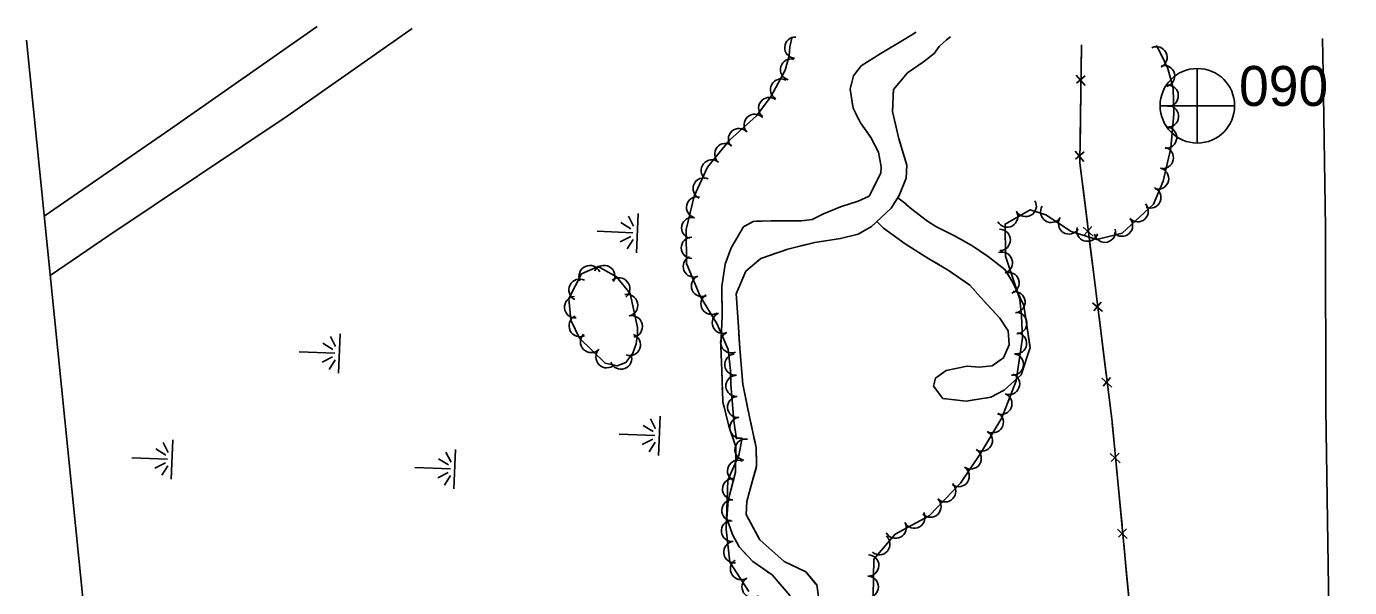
# Model space of a CAD drawing. Extents: x 296487 to 298842, y 31545 to 32791.
# Drawn here: x 297235.4 to 297732.5, y 32554.5 to 32765.2 of the extents above; entities that cross this region are included whole.
import ezdxf

# ---------------------------------------------------------------- set-up
doc = ezdxf.new("R2010")
doc.units = 0
for name, color, linetype in [('Level 11', 7, 'Continuous'), ('Level 15', 7, 'Continuous'), ('Level 18', 7, 'Continuous'), ('Level 19', 7, 'Continuous'), ('Level 4', 7, 'Continuous')]:
    doc.layers.add(name, color=color, linetype=linetype)

msp = doc.modelspace()

# ---------------------------------------------------------------- linework, layer by layer
at = {"layer": 'Level 11'}
for points in [[(297344.7, 32765.17), (297289.65, 32726.69), (297242.1, 32694)], [(297244.35, 32671.7), (297266.42, 32686.72), (297333.33, 32731.54), (297380.29, 32764.39)], [(297732.45, 31749.54), (297732.24, 31791.84), (297732.13, 31829.29), (297731.83, 31872.75), (297730.81, 31924.68), (297730.53, 31968.01), (297729.53, 32021.42), (297729.12, 32084.97), (297728.52, 32147.82), (297727.87, 32212.59), (297727.19, 32277.97), (297726.38, 32352.97), (297725.93, 32414.91), (297724.99, 32486.15), (297724.55, 32554.59), (297723.53, 32621.52), (297723.38, 32689.57), (297722.58, 32747.62), (297722.25, 32760.6)]]:
    msp.add_lwpolyline(points, dxfattribs=at)
at = {"layer": 'Level 15'}
for p, q in [((297629.82, 32746.9), (297633.09, 32743.05)), ((297633.14, 32746.68), (297629.85, 32743.86)), ((297629.43, 32718.37), (297632.7, 32714.52)), ((297632.75, 32718.15), (297629.46, 32715.33)), ((297632.38, 32689.78), (297636.14, 32686.41)), ((297635.69, 32690.02), (297632.82, 32686.77)), ((297635.89, 32661.47), (297639.66, 32658.1)), ((297639.21, 32661.7), (297636.34, 32658.46)), ((297639.41, 32633.15), (297643.17, 32629.78)), ((297642.72, 32633.39), (297639.85, 32630.14)), ((297642.59, 32604.85), (297646.26, 32601.38)), ((297645.91, 32604.99), (297642.95, 32601.83)), ((297645.32, 32576.45), (297648.98, 32572.97)), ((297648.64, 32576.59), (297645.68, 32573.43))]:
    msp.add_line(p, q, dxfattribs=at)
for points in [[(297631.76, 32758.26), (297631.16, 32714.05), (297643.24, 32616.74), (297653.23, 32512.59), (297661.32, 32428.35), (297662.84, 32377.26), (297663.95, 32360.48)], [(297631.76, 32758.26), (297631.62, 32748.07)], [(297631.53, 32741.32), (297631.37, 32729.73)], [(297631.37, 32729.73), (297631.23, 32719.53)], [(297631.31, 32712.8), (297632.74, 32701.3)], [(297632.74, 32701.3), (297634, 32691.18)], [(297634.83, 32684.49), (297636.26, 32672.98)], [(297636.26, 32672.98), (297637.52, 32662.86)], [(297638.35, 32656.17), (297639.78, 32644.67)], [(297639.78, 32644.67), (297641.03, 32634.55)], [(297641.86, 32627.86), (297643.24, 32616.74), (297643.28, 32616.35)], [(297643.28, 32616.35), (297644.25, 32606.2)], [(297644.9, 32599.49), (297646, 32587.95)], [(297646, 32587.95), (297646.98, 32577.8)], [(297647.62, 32571.09), (297648.73, 32559.55)], [(297648.73, 32559.55), (297649.7, 32549.4)]]:
    msp.add_lwpolyline(points, dxfattribs=at)
at = {"layer": 'Level 18'}
for points in [[(297523.03, 32761.23), (297522.17, 32757.58), (297521.98, 32754.18), (297520.43, 32748.77), (297515.16, 32738.99), (297509.67, 32731.67), (297499.51, 32722.5), (297491.23, 32712.4), (297486.22, 32701.52), (297483.23, 32688.9), (297483.35, 32676.23), (297488.53, 32663.94), (297494.95, 32653.42), (297499.05, 32643.89), (297499.88, 32635.95), (297500, 32630.9), (297501.11, 32617.05), (297502.18, 32610.26)], [(297553.45, 32551.33), (297553.79, 32565.22), (297561.74, 32574.51), (297574.58, 32581.47), (297586.31, 32593.65), (297593.84, 32604.78), (297601.8, 32618.18), (297607.25, 32632.15), (297609.57, 32648.32), (297609.26, 32656.37), (297608.55, 32662.73), (297603.22, 32678.98), (297603.06, 32690.98), (297612.53, 32696.33), (297618.31, 32694.41), (297627.94, 32688.18), (297637.5, 32685.21), (297646.98, 32687.57), (297658.82, 32698.46), (297662.43, 32707.11), (297665.28, 32719.47), (297666.43, 32732.34), (297666.15, 32741.99), (297664.23, 32749.36), (297661.73, 32754.64), (297660.26, 32757.33), (297659.87, 32757.97)], [(297462.25, 32664.95), (297457.09, 32671.19), (297450.23, 32675.11), (297443.93, 32672.32), (297439.22, 32662.98), (297439.88, 32654.92), (297443.21, 32648.13), (297452.77, 32638.7), (297457.33, 32637.74), (297460.61, 32638.98), (297463.17, 32642.49), (297464.44, 32646.04), (297464.98, 32649.81), (297465.01, 32652.17), (297462.25, 32664.95)], [(297504.23, 32610.58), (297503.08, 32604.19), (297498.93, 32594.78), (297498.3, 32576.43), (297499.68, 32564.06), (297506.8, 32553.05)]]:
    msp.add_lwpolyline(points, dxfattribs=at)
for centre, radius, start, end in [((297524.24, 32757.23), 3.98, 86.7381, 266.7228), ((297659.92, 32753.57), 4.01, 295.344, 115.3287), ((297522.66, 32749), 3.98, 74.0077, 253.9924), ((297662.79, 32746.55), 4.01, 284.5659, 104.5505), ((297518.88, 32741.51), 3.98, 61.6992, 241.6839), ((297664.13, 32739.18), 4.01, 271.6707, 91.6554), ((297514.43, 32734.55), 3.98, 53.1365, 233.1212), ((297664.24, 32731.42), 4.01, 264.9152, 84.8999), ((297508.99, 32728.25), 3.98, 42.0926, 222.0773), ((297503.08, 32722.91), 3.98, 42.0926, 222.0773), ((297663.53, 32723.45), 4.01, 264.9152, 84.8999), ((297497.93, 32717.28), 3.98, 50.6531, 230.6378), ((297662.29, 32715.84), 4.01, 257.0415, 77.0262), ((297492.88, 32711.12), 3.98, 50.6531, 230.6378), ((297660.5, 32708.04), 4.01, 257.0415, 77.0262), ((297489.82, 32704.35), 3.98, 65.2953, 245.28), ((297657.59, 32700.96), 4.01, 247.3036, 67.2883), ((297487.35, 32697.25), 3.98, 76.6819, 256.6666), ((297610.8, 32697.76), 4.01, 209.4808, 29.4654), ((297603.82, 32693.82), 4.01, 209.4808, 29.4654), ((297620.38, 32695.57), 4.01, 147.0797, 327.0644), ((297652.85, 32695.82), 4.01, 222.6142, 42.5988), ((297485.52, 32689.5), 3.98, 76.6819, 256.6666), ((297627.11, 32691.21), 4.01, 147.0797, 327.0644), ((297633.97, 32688.5), 4.01, 162.7475, 342.7322), ((297640.54, 32688.13), 4.01, 194.0155, 14.0001), ((297646.96, 32690.4), 4.01, 222.6142, 42.5988), ((297485.38, 32682.07), 3.98, 90.5275, 270.5122), ((297601.04, 32685.01), 4.01, 270.7619, 90.7466), ((297601.83, 32676.47), 4.01, 288.1872, 108.1719), ((297447.06, 32671.37), 4.08, 23.8806, 203.8653), ((297452.42, 32671.39), 4.08, 330.279, 150.2636), ((297486.1, 32675.06), 3.98, 112.8757, 292.8604), ((297443.27, 32666.28), 4.08, 63.2198, 243.2045), ((297458, 32666.74), 4.08, 309.6039, 129.5885), ((297489.2, 32667.72), 3.98, 112.8757, 292.8604), ((297604.33, 32668.86), 4.01, 288.1872, 108.1719), ((297461.02, 32660.51), 4.08, 282.1911, 102.1758), ((297492.78, 32660.98), 3.98, 121.3861, 301.3708), ((297606.56, 32661.63), 4.01, 276.3558, 96.3404), ((297441.62, 32659.78), 4.08, 94.7501, 274.7348), ((297443.32, 32652.75), 4.08, 116.0743, 296.059), ((297462.74, 32652.53), 4.08, 282.1911, 102.1758), ((297497.01, 32653.9), 3.98, 113.323, 293.3077), ((297607.26, 32653.81), 4.01, 272.2133, 92.1979), ((297447.6, 32646.8), 4.08, 135.4481, 315.4328), ((297462.04, 32645.67), 4.08, 250.3242, 70.3089), ((297500.16, 32646.58), 3.98, 113.323, 293.3077), ((297607.15, 32646.21), 4.01, 261.8453, 81.83), ((297453.42, 32641.07), 4.08, 135.4481, 315.4328), ((297458.73, 32640.55), 4.08, 200.7035, 20.6881), ((297501.74, 32638.21), 3.98, 95.9389, 275.9236), ((297606.01, 32638.28), 4.01, 261.8453, 81.83), ((297604.53, 32630.94), 4.01, 248.7249, 68.7096), ((297502.14, 32630.21), 3.98, 94.5901, 274.5748), ((297502.78, 32622.27), 3.98, 94.5901, 274.5748), ((297601.62, 32623.47), 4.01, 248.7249, 68.7096), ((297598.4, 32616.55), 4.01, 239.2589, 59.2435), ((297503.62, 32614.52), 3.98, 98.9439, 278.9286), ((297505.59, 32606.27), 4.01, 79.7565, 259.7411), ((297594.3, 32609.67), 4.01, 239.2589, 59.2435), ((297590.1, 32602.99), 4.01, 235.9687, 55.9534), ((297502.77, 32598.3), 4.01, 66.2074, 246.1921), ((297585.61, 32596.36), 4.01, 235.9687, 55.9534), ((297500.91, 32591.47), 4.01, 88.0653, 268.05), ((297580.53, 32590.67), 4.01, 226.0663, 46.0509), ((297500.64, 32583.46), 4.01, 88.0653, 268.05), ((297574.98, 32584.9), 4.01, 226.0663, 46.0509), ((297500.49, 32575.77), 4.01, 96.3682, 276.3529), ((297568.95, 32580.8), 4.01, 208.4825, 28.4672), ((297561.91, 32576.98), 4.01, 208.4825, 28.4672), ((297501.37, 32567.81), 4.01, 96.3682, 276.3529), ((297555.81, 32570.8), 4.01, 229.4358, 49.4205), ((297551.63, 32562.81), 4.01, 268.6008, 88.5855), ((297503.87, 32561.44), 4.01, 122.8978, 302.8825), ((297508.22, 32554.72), 4.01, 122.8978, 302.8825), ((297551.44, 32554.8), 4.01, 268.6008, 88.5855)]:
    msp.add_arc(centre, radius, start, end, dxfattribs=at)
at = {"layer": 'Level 19'}
for p, q in [((297464.58, 32680.22), (297465.18, 32695.01)), ((297462.52, 32689.17), (297458.76, 32691.53)), ((297461.56, 32694), (297463.5, 32690.23)), ((297449.82, 32688.26), (297463.23, 32687.71)), ((297462.41, 32686.37), (297458.47, 32684.33)), ((297461.06, 32681.63), (297463.3, 32685.23)), ((297352.64, 32634.97), (297353.24, 32649.75)), ((297350.58, 32643.91), (297346.82, 32646.27)), ((297349.62, 32648.74), (297351.56, 32644.97)), ((297337.88, 32643), (297351.29, 32642.45)), ((297350.46, 32641.11), (297346.53, 32639.07)), ((297349.11, 32636.37), (297351.35, 32639.97)), ((297470.81, 32613.04), (297467.05, 32615.39)), ((297469.85, 32617.87), (297471.79, 32614.1)), ((297472.87, 32604.09), (297473.47, 32618.87)), ((297289.79, 32595.24), (297290.39, 32610.02)), ((297458.11, 32612.12), (297471.52, 32611.58)), ((297470.69, 32610.24), (297466.76, 32608.19)), ((297287.73, 32604.18), (297283.97, 32606.54)), ((297286.77, 32609.01), (297288.71, 32605.24)), ((297393.01, 32605.35), (297394.95, 32601.58)), ((297396.03, 32591.58), (297396.63, 32606.36)), ((297469.35, 32605.5), (297471.58, 32609.1)), ((297275.03, 32603.27), (297288.44, 32602.72)), ((297287.61, 32601.38), (297283.68, 32599.34)), ((297286.27, 32596.65), (297288.5, 32600.24)), ((297381.27, 32599.61), (297394.68, 32599.06)), ((297393.97, 32600.52), (297390.21, 32602.88)), ((297393.85, 32597.72), (297389.92, 32595.68)), ((297392.51, 32592.99), (297394.74, 32596.58))]:
    msp.add_line(p, q, dxfattribs=at)
for points in [[(297569.6, 32763), (297565.11, 32760.32), (297556.08, 32754.87), (297549.02, 32750.34), (297546.07, 32746.63), (297544.8, 32741.57), (297545.96, 32734.47), (297548.77, 32729.03), (297552.66, 32723.54), (297555.54, 32718.04), (297556.52, 32712.45), (297556.32, 32710.21), (297554.94, 32707.1), (297552.01, 32701.43)], [(297569.6, 32763), (297565.11, 32760.32), (297556.08, 32754.87), (297549.02, 32750.34), (297546.44, 32747.09)], [(297552.88, 32690.12), (297560.32, 32696.91), (297563.33, 32701.65), (297565.95, 32708.16), (297566.14, 32713.15), (297563.12, 32722.99), (297560.78, 32733.26), (297561.08, 32741.51), (297566.42, 32747.81), (297572.42, 32751.9), (297576.44, 32755.03), (297578.3, 32757.67), (297581.01, 32760.18), (297582.53, 32761.26)], [(297561.01, 32739.67), (297561.08, 32741.51), (297566.42, 32747.81), (297572.42, 32751.9), (297576.44, 32755.03), (297578.3, 32757.67), (297581.01, 32760.18), (297582.53, 32761.26)], [(297545.26, 32743.42), (297544.8, 32741.57), (297544.81, 32741.52)], [(297545.44, 32737.67), (297545.75, 32735.74)], [(297560.79, 32733.21), (297560.78, 32733.26), (297560.86, 32735.36)], [(297547.16, 32732.14), (297548.05, 32730.41)], [(297562.23, 32726.9), (297561.75, 32729)], [(297550.13, 32727.11), (297552.66, 32723.54), (297555.54, 32718.04), (297556.52, 32712.45), (297556.32, 32710.21), (297554.94, 32707.1), (297552.01, 32701.43)], [(297563.84, 32720.65), (297563.21, 32722.71)], [(297562.83, 32700.85), (297563.33, 32701.65), (297565.95, 32708.16), (297566.14, 32713.15), (297565.1, 32716.53)], [(297522.33, 32551.35), (297515.52, 32559.25), (297508.24, 32564.26), (297503.2, 32569.74), (297500.68, 32574.39), (297498.54, 32580.42), (297499.04, 32587.14), (297501.76, 32597.89), (297501.88, 32607.33), (297499.32, 32615.15), (297496.99, 32624.32), (297496.66, 32635.92), (297496.24, 32645.14), (297496.73, 32656.47), (297496.71, 32667.6), (297497.92, 32675.92), (297500.22, 32682.11), (297504.73, 32689.91), (297508.38, 32691.99), (297515.15, 32692.18), (297522.06, 32692.18), (297526.62, 32692.23), (297530.61, 32692.69), (297534.9, 32694.86), (297541.2, 32697.42), (297547.9, 32699.62), (297552.01, 32701.43)], [(297526.59, 32692.23), (297526.62, 32692.23), (297530.61, 32692.69), (297534.9, 32694.86), (297541.2, 32697.42), (297547.9, 32699.62), (297552.01, 32701.43)], [(297554.93, 32691.99), (297557.42, 32689.47), (297565.52, 32683.54), (297574.43, 32677.94), (297581.69, 32673.71), (297589.78, 32668.07), (297593.87, 32663.51), (297601.08, 32655.63), (297604.16, 32650.85), (297604.57, 32645.61), (297602.46, 32640.74), (297598.18, 32637.81), (297593.35, 32637.31), (297588.76, 32637.66), (297580.95, 32636.05), (297576.95, 32633.15), (297576.22, 32630.1), (297579.72, 32625.48), (297588.44, 32624.52), (297597.66, 32625.94), (297602.76, 32628.57), (297609.05, 32634.34), (297612.48, 32644.58), (297610.05, 32660.38), (297605.94, 32669.02), (297603, 32673.93), (297596.78, 32678.72), (297590.59, 32682.91), (297584.06, 32686.56), (297577.02, 32690.09), (297573.86, 32692.1), (297570.72, 32694.5), (297568.08, 32696.6), (297565.94, 32698.31), (297565.78, 32698.63), (297562.83, 32700.85)], [(297586.37, 32685.27), (297584.06, 32686.56), (297577.02, 32690.09), (297573.86, 32692.1), (297570.72, 32694.5), (297568.08, 32696.6), (297565.94, 32698.31), (297565.78, 32698.63), (297562.83, 32700.85)], [(297496.71, 32666.22), (297496.71, 32667.6), (297497.92, 32675.92), (297500.22, 32682.11), (297504.73, 32689.91), (297506.28, 32690.8)], [(297552.88, 32690.12), (297547.85, 32687.17), (297541.18, 32685.54), (297531.56, 32684.08), (297521.42, 32681.59), (297511.32, 32678.07), (297505.62, 32673.35), (297502.1, 32664.75), (297502.74, 32654.38), (297503.41, 32644.2), (297504.51, 32630.81), (297507.17, 32617.95), (297509.52, 32607.15), (297509.7, 32600.1), (297508.09, 32594.24), (297506.01, 32586.83), (297505.77, 32581.95), (297510.92, 32572.45), (297520.13, 32564.28), (297528.22, 32560.37), (297532.29, 32555.48), (297533.35, 32548.35)], [(297509.72, 32692.03), (297511.59, 32692.08)], [(297515.34, 32692.18), (297517.22, 32692.18)], [(297520.97, 32692.18), (297522.06, 32692.18), (297522.84, 32692.19)], [(297552.88, 32690.12), (297547.85, 32687.17), (297541.18, 32685.54), (297531.56, 32684.08), (297526.19, 32682.76)], [(297552.88, 32690.12), (297554.23, 32691.35)], [(297554.93, 32691.99), (297557.42, 32689.47), (297565.52, 32683.54), (297574.43, 32677.94), (297578.12, 32675.79)], [(297516.95, 32680.03), (297515.13, 32679.4)], [(297522.44, 32681.84), (297521.42, 32681.59), (297520.59, 32681.3)], [(297591.45, 32682.32), (297590.59, 32682.91), (297589.79, 32683.35)], [(297596.32, 32679.03), (297594.7, 32680.13)], [(297507, 32674.5), (297505.62, 32673.35), (297502.1, 32664.75), (297502.74, 32654.38), (297503.17, 32647.92)], [(297511.49, 32678.13), (297511.32, 32678.07), (297509.97, 32676.96)], [(297600.99, 32675.48), (297599.44, 32676.67)], [(297581.5, 32673.82), (297581.69, 32673.71), (297583.11, 32672.72)], [(297586.33, 32670.48), (297587.93, 32669.36)], [(297612.26, 32646.07), (297610.05, 32660.38), (297605.94, 32669.02), (297603.71, 32672.74)], [(297496.52, 32639.04), (297496.24, 32645.14), (297496.73, 32656.47), (297496.71, 32666.22)], [(297590.89, 32666.83), (297592.2, 32665.38)], [(297594.83, 32662.47), (297601.08, 32655.63), (297604.16, 32650.85), (297604.57, 32645.61), (297602.46, 32640.74), (297600.09, 32639.12)], [(297503.17, 32647.92), (297503.41, 32644.2), (297504.51, 32630.81), (297506.7, 32620.24)], [(297595.87, 32625.67), (297597.66, 32625.94), (297602.76, 32628.57), (297609.05, 32634.34), (297612.48, 32644.58), (297612.26, 32646.07)], [(297496.73, 32633.42), (297496.68, 32635.3)], [(297600.09, 32639.12), (297598.18, 32637.81), (297593.35, 32637.31), (297588.76, 32637.66), (297580.95, 32636.05), (297576.95, 32633.15), (297576.22, 32630.1), (297576.55, 32629.65)], [(297496.89, 32627.8), (297496.84, 32629.67)], [(297578.92, 32626.53), (297579.72, 32625.48), (297580.35, 32625.41)], [(297584.24, 32624.98), (297586.19, 32624.76)], [(297590.07, 32624.77), (297592, 32625.07)], [(297497.52, 32622.24), (297497.06, 32624.06)], [(297500.3, 32592.11), (297501.76, 32597.89), (297501.88, 32607.33), (297499.32, 32615.15), (297498.44, 32618.6)], [(297507.49, 32616.47), (297507.9, 32614.58)], [(297508.72, 32610.82), (297509.13, 32608.93)], [(297509.57, 32605.12), (297509.62, 32603.19)], [(297509.5, 32599.37), (297508.09, 32594.24), (297506.01, 32586.83), (297505.77, 32581.95), (297510.57, 32573.11)], [(297505.66, 32567.06), (297503.2, 32569.74), (297500.68, 32574.39), (297498.54, 32580.42), (297499.04, 32587.14), (297500.3, 32592.11)], [(297510.57, 32573.11), (297510.92, 32572.45), (297520.13, 32564.28), (297528.22, 32560.37), (297532, 32555.83)], [(297509.74, 32563.23), (297508.24, 32564.26), (297508.2, 32564.3)], [(297514.37, 32560.04), (297512.83, 32561.1)], [(297518.28, 32556.05), (297517.06, 32557.47)]]:
    msp.add_lwpolyline(points, dxfattribs=at)
at = {"layer": 'Level 4'}
for p, q in [((297675.24, 32749.42), (297675.18, 32721.57)), ((297661.33, 32735.39), (297689.24, 32735.38))]:
    msp.add_line(p, q, dxfattribs=at)
msp.add_lwpolyline([(297235.43, 32760.04), (297336.59, 31758.44)], dxfattribs=at)
msp.add_circle((297675.3, 32735.4), 14, dxfattribs=at)

# ---------------------------------------------------------------- texts
msp.add_text('090', height=15, dxfattribs=at).set_placement((297690.95, 32735.33))

doc.saveas('drawing.dxf')
